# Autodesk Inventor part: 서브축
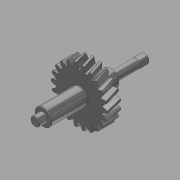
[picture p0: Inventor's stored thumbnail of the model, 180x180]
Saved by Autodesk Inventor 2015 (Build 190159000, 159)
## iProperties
Created: 2017-11
Part Number: 서브축
Material: 강철, 탄소
Document SubType Name: Modeling
Designer: mduedu
Categories: <?xml version="1.0" encoding="UTF-16"?> <MemberInstance><Categories><FamilyTemplate><FamilyTemplateParameter ValueType="xs:double" Id="1" ObjectReferenceKey="da
Density: 7.87 g/cm^3
Appearance: 반광택
Mass: 233.4 g
Surface Area: 98.1276 cm^2
Volume: 29.657 cm^3
CustomPartVersion: 1
Author: mduedu
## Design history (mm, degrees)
sketch "Sketch1"
  geometry: C1 r 24.776 at (0, 0)
  constraints: 1 centre point
  dimensions: "d0" = 49.55215 diameter of C1 (= da_da)
extrude "Extrusion1" new body sketch "Sketch1" distance "d1" = 12 (= da_b); taper "d2" = 0 deg
workplane "Work Plane2"
sketch "Sketch2"
  geometry: C1 r 24.776 at (0, 0) reference; C2 r 22.776 at (0, 0)
  constraints: 1 centre point, 1 coincident
  dimensions: "d3" = 45.55215 diameter of C2 (= da_dw)
feature "피치 지름" sketch "Sketch2" dims "d4" = 10, "d5" = 0
workplane "Work Plane8"
workplane "Work Plane9"
feature "스퍼 기어" dims "da_b" = 12, "da_d" = 45.55215, "da_aw" = 54.86964, "da_da" = 49.55215, "da_df" = 40.55215, "da_dw" = 45.55215, angle "da_beta" = 15 deg, "da_lefttooth" = 10, "da_righttooth" = 0
sketch "스케치3"
  geometry: C1 r 7.5 at (0, 0); 1 further point
  constraints: 1 centre point, 1 coincident
  dimensions: "d49" = 15 diameter of C1
extrude "돌출2" join sketch "스케치3" distance "d50" = 32; taper "d51" = 0 deg
sketch "스케치4"
  geometry: C1 r 4 at (0, 0); 1 further point
  constraints: 1 centre point, 1 coincident
  dimensions: "d52" = 8 diameter of C1
extrude "돌출3" join sketch "스케치4" distance "d53" = 7; taper "d54" = 0 deg
sketch "스케치5"
  geometry: C1 r 7.5 at (0, 0); 1 further point
  constraints: 1 centre point, 1 coincident
  dimensions: "d55" = 15 diameter of C1
extrude "돌출4" join sketch "스케치5" distance "d56" = 16; taper "d57" = 0 deg
sketch "스케치6"
  geometry: C1 r 4 at (0, 0); 1 further point
  constraints: 1 centre point, 1 coincident
  dimensions: "d58" = 8 diameter of C1
extrude "돌출5" join sketch "스케치6" distance "d59" = 30; taper "d60" = 0 deg
chamfer "모따기1" distance "d61" = 0.5; stored, may be unused: second distance "d62" = 2, angle "d63" = 45 deg
fillet "모깎기1" dims "d64" = 0.5
sketch "스케치7"
  geometry: L1 (-3.25, -3.25)-(3.25, -3.25); L2 (3.25, -3.25)-(3.25, 3.25); L3 (3.25, 3.25)-(-3.25, 3.25); L4 (-3.25, 3.25)-(-3.25, -3.25); L5 (-3.25, -3.25)-(3.25, 3.25); L6 (3.25, -3.25)-(-3.25, 3.25); L7 (-5, -5)-(5, -5); L8 (5, -5)-(5, 5); L9 (5, 5)-(-5, 5); L10 (-5, 5)-(-5, -5); L11 (-5, -5)-(5, 5); L12 (5, -5)-(-5, 5); 1 further point
  constraints: 24 end point, 4 midpoint, 4 parallel, 2 horizontal, 2 perpendicular
  dimensions: "d65" = 6.5 distance of L3.end L2.end; "d66" = 6.5 distance of L2.end L1.end; "d67" = 10 distance of L9.end L8.end; "d68" = 10 distance of L8.end L7.end
extrude "돌출6" cut sketch "스케치7" distance "d69" = 8; taper "d70" = 0 deg
body "Solid1"
body "Srf1"
other parameters: "d16" = 54.86964 (= da_aw), "d17" = 0, "d34" = 1.428 (computed from da_z), "d39" = 0, "d41" = 0, "d43" = 54.86964 (= da_aw), "d46" = 54.86964 (= da_aw), "d47" = 0, "d48" = 0
